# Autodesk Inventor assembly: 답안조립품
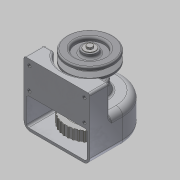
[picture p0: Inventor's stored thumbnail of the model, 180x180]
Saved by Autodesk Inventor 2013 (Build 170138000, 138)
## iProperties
Created: 2015-02
Part Number: 답안조립품
Document SubType Name: Assembly
Designer: Administrator
Author: Administrator
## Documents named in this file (14)
- C:\Users\Administrator\Desktop\450216V1001\답안조립품.iam
- C:\Users\Administrator\Desktop\450216V1001\본체.ipt
- C:\Users\Administrator\Desktop\450216V1001\베어링 6001.ipt
- C:\Users\Administrator\Desktop\450216V1001\스퍼기어.ipt
- C:\Users\Administrator\Desktop\450216V1001\축.ipt
- C:\Users\Administrator\Desktop\450216V1001\키5x5.ipt
- C:\Users\Administrator\Desktop\450216V1001\키4x4.ipt
- C:\Users\Administrator\Desktop\450216V1001\오일실.ipt
- C:\Users\Administrator\Desktop\450216V1001\축커버.ipt
- C:\Users\Administrator\Desktop\450216V1001\M3x0.5.ipt
- C:\Users\Administrator\Desktop\450216V1001\V-벨트풀리.ipt
- C:\Users\Administrator\Desktop\450216V1001\와샤.ipt
- C:\Users\Administrator\Desktop\450216V1001\M5x0.8.ipt
- M5x0.8.ipt
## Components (6 placed, 3 different names)
1. V-벨트풀리:1 — 각도:4, 플러쉬:1
2. M5x0.8:1
3. M3x0.5:1
4. M3x0.5:2
5. M3x0.5:3
6. M3x0.5:4
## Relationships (2: Angle 1, Flush 1)
- 각도:4 [Angle]: V-벨트풀리:1
- 플러쉬:1 [Flush]: V-벨트풀리:1
